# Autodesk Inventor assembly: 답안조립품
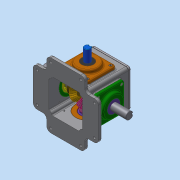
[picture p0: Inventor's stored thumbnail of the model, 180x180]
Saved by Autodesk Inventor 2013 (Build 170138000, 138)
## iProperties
Created: 2019-12
Part Number: 답안조립품
Document SubType Name: Assembly
Designer: dgall
Author: dgall
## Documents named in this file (16)
- C:\Users\dgall\Desktop\391204V1044\답안조립품.iam
- C:\Users\dgall\Desktop\391204V1044\본체.ipt
- C:\Users\dgall\Desktop\391204V1044\메인커버.ipt
- C:\Users\dgall\Desktop\391204V1044\서브커버.ipt
- C:\Users\dgall\Desktop\391204V1044\베어링 6204.ipt
- C:\Users\dgall\Desktop\391204V1044\베어링 6203.ipt
- C:\Users\dgall\Desktop\391204V1044\메인축.ipt
- C:\Users\dgall\Desktop\391204V1044\키 4x4.ipt
- C:\Users\dgall\Desktop\391204V1044\메인베벨기어.ipt
- C:\Users\dgall\Desktop\391204V1044\오일 실 20 35 8.ipt
- C:\Users\dgall\Desktop\391204V1044\서브축.ipt
- C:\Users\dgall\Desktop\391204V1044\서브베벨기어.ipt
- C:\Users\dgall\Desktop\391204V1044\오일 실 17 32 8.ipt
- C:\Users\dgall\Desktop\391204V1044\개스킷.ipt
- C:\Users\dgall\Desktop\391204V1044\상부커버.ipt
- C:\Users\dgall\Desktop\391204V1044\볼트 M4.ipt
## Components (1 placed, 1 different names)
1. 개스킷:1
